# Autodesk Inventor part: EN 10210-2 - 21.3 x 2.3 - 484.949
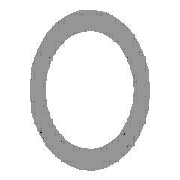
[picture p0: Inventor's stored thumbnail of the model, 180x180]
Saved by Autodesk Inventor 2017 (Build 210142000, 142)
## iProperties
Created: 2017-11
Part Number: EN 10210-2 - 21.3 x 2.3 - 484.949
Material: Steel, Mild
Description: Pipe
Document SubType Name: Modeling
Standard: DIN
Designer: iusti
Standard Revision: 2006-07
Standards Organization: DIN
Language: en-US
Size Designation: 21.3 x 2.3
Categories: <MemberInstance><Categories><Category DisplayName="Structural Shapes" InternalName="089c4875-fa83-4c05-b084-43b9cc11f5ed" Mnemonic="GRDR"><CategoryParameter Dis
Stock Number: 21.3 x 2.3
Density: 7.85 g/cm^3
Appearance: Semi-Polished
_CCFamilyMember: 1
_CCFamilyDisplayName: DIN EN 10210-2 - Pipe
_FrameMemberDoc: Frame Member File
_Version: 15.0.0
_GetPNFromCC: 1
IsCustomPart: 1
Author: iusti
G_L: 484.949 mm
G_W: 21.300 mm
G_H: 21.300 mm
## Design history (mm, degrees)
node "Start plane"
node "End plane"
sketch "Sketch"
  geometry: C1 r 8.35 at (0, 0); C2 r 10.65 at (0, 0); 2 further points
  constraints: 3 coincident, 2 centre point
  dimensions: "d0" = 21.3 diameter of C2 (= G_H); "d1" = 2.3 radial gap between concentric circles of C2 C1 (= G_T)
extrude "Body" new body sketch "Sketch" stored distance "d2" = 484.9487 (= G_L); taper "d3" = 0 deg
node "Driven Length"
  sketch "Sketch3"
    geometry: L1 (0, 0)-(10, 0) reference
    constraints: 2 end point, 1 horizontal
  workplane "Work Plane3"
  sketch "Sketch4"
    geometry: L1 (-2, 0)-(12, 0) reference; L2 (-2, 484.949)-(12, 484.949) reference
    dimensions: "d7" = 484.9487 distance between parallel lines of L1 L2 (derived)
body "Solid1"
other parameters: "G_H" = 21.3 [user parameter; used in 1 equation term], "G_T" = 2.3 [user parameter; used in 1 equation term], "G_L" = 484.9487 (= d7) [user parameter; used in 1 equation term], "G_OFFSET_START" = 0 [user parameter; used in 1 equation term], "G_OFFSET_END" = 0 [user parameter; used in 1 equation term], "d4" = 0 (computed from G_OFFSET_START), "d5" = 484.9487 (= G_OFFSET_END + B_L), "B_L" = 484.9487 [user parameter; used in 1 equation term], "d6" = 90 deg
